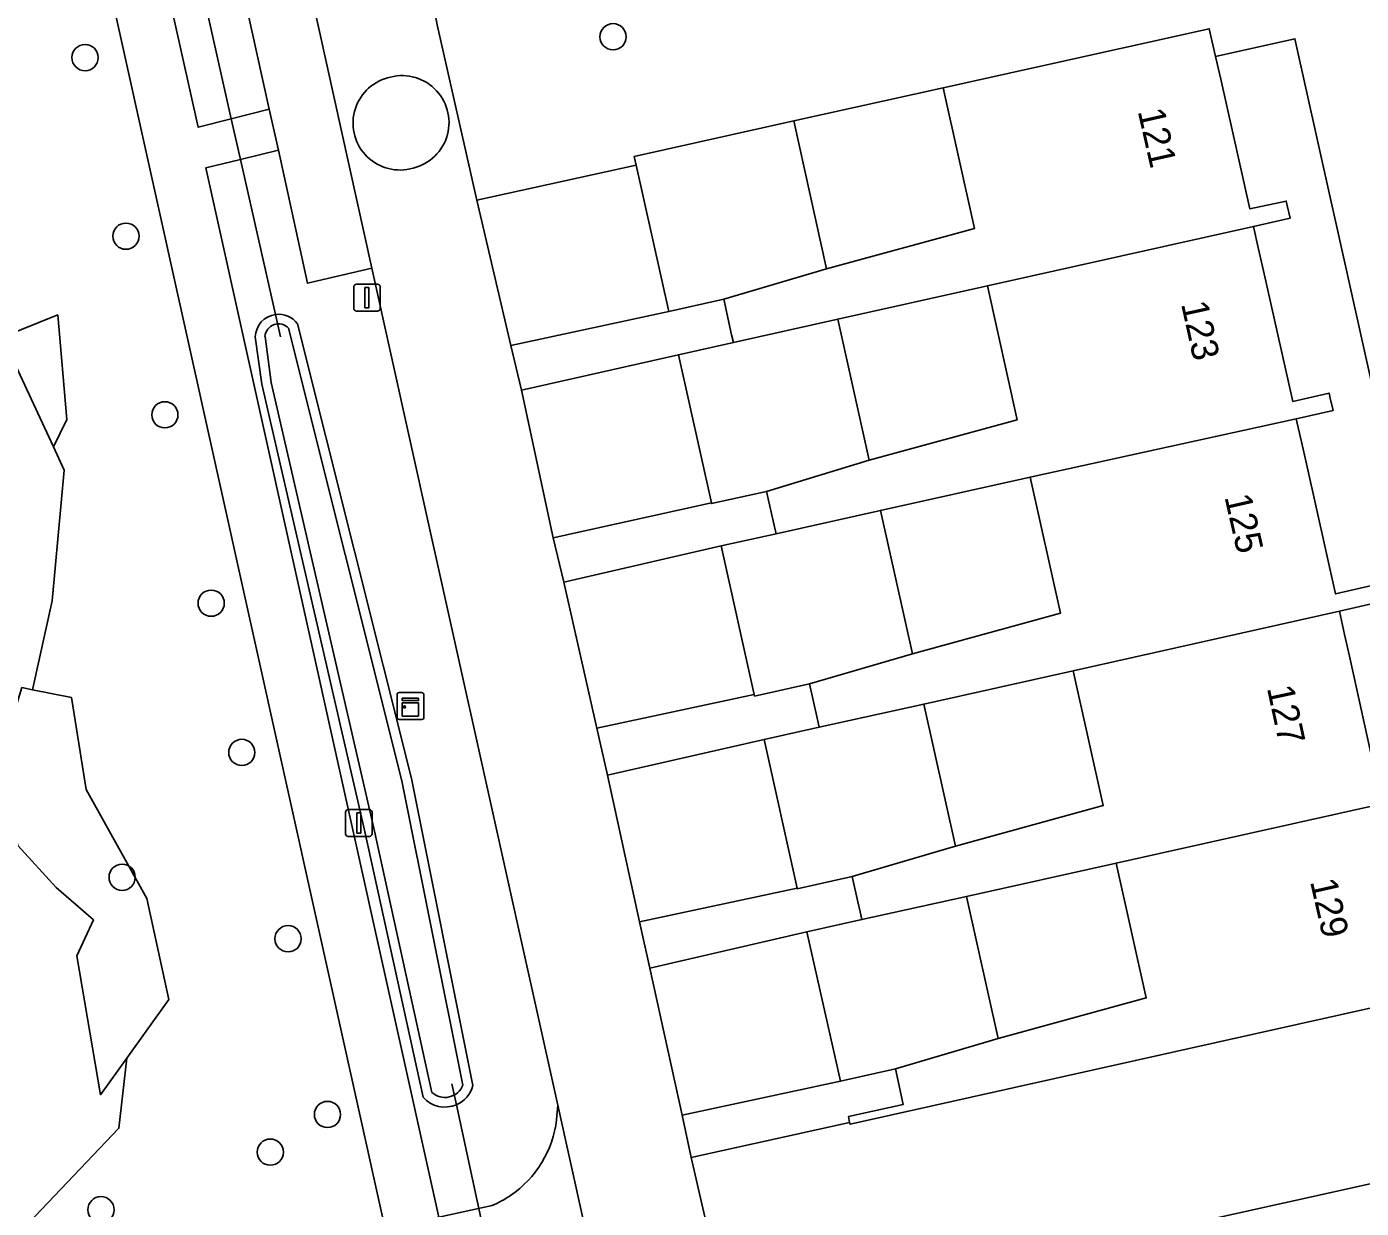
# Model space of a CAD drawing. Extents: x 156661 to 157576, y 383570 to 384425.
# Drawn here: x 156780.23 to 156829.98, y 383941.52 to 383985.58 of the extents above; entities that cross this region are included whole.
import ezdxf

# ---------------------------------------------------------------- set-up
doc = ezdxf.new("R2010")
doc.units = 0
for name, color, linetype in [('IMGEO_Berm_groen', 7, 'Continuous'), ('IMGEO_Boom', 7, 'Continuous'), ('IMGEO_Duiker', 7, 'Continuous'), ('IMGEO_Erf', 7, 'Continuous'), ('IMGEO_Groenvoorziening', 7, 'Continuous'), ('IMGEO_Kast', 7, 'Continuous'), ('IMGEO_Lichtmast', 7, 'Continuous'), ('IMGEO_Meer_plas_ven_vijver', 7, 'Continuous'), ('IMGEO_Muur', 7, 'Continuous'), ('IMGEO_Oever', 7, 'Continuous'), ('IMGEO_Pand', 7, 'Continuous'), ('IMGEO_Pand_nummerreeks', 7, 'Continuous'), ('IMGEO_Parkeervlak_open', 7, 'Continuous'), ('IMGEO_Rijbaan_lokaal_gesloten', 7, 'Continuous'), ('IMGEO_Rijbaan_lokaal_open', 7, 'Continuous'), ('IMGEO_Voetpad_open', 7, 'Continuous'), ('IMGEO_Waterloop', 7, 'Continuous')]:
    doc.layers.add(name, color=color, linetype=linetype)

msp = doc.modelspace()

# ---------------------------------------------------------------- linework, layer by layer
at = {"layer": 'IMGEO_Berm_groen'}
for points in [[(156795.637, 383965.148), (156795.252, 383966.882), (156793.102, 383976.569), (156790.698, 383976.013), (156789.615, 383980.975), (156788.201, 383980.63), (156786.905, 383980.313), (156795.59, 383941.189), (156797.583, 383941.621)], [(156790.324, 383974.498), (156794.571, 383957.54)], [(156795.006, 383945.664), (156792.825, 383955.613), (156788.991, 383972.249), (156788.754, 383974.011)], [(156799.984, 383944.824), (156800.028, 383945.365), (156795.637, 383965.148)], [(156794.571, 383957.54), (156796.861, 383946.093)]]:
    msp.add_lwpolyline(points, dxfattribs=at)
for centre, radius, start, end in [((156789.624, 383973.982), 0.871, 97.793, 178.0581), ((156789.622, 383973.979), 0.873, 36.4787, 97.6662), ((156795.822, 383946.369), 1.075, 293.447, 345.1249), ((156795.819, 383946.367), 1.075, 220.8788, 293.664), ((156796.012, 383945.301), 4.001, 304.3465, 353.1493), ((156796.056, 383945.213), 3.903, 293.0369, 304.5462)]:
    msp.add_arc(centre, radius, start, end, dxfattribs=at)
at = {"layer": 'IMGEO_Boom'}
for centre in [(156802.09, 383985.2), (156782.407, 383984.424), (156783.931, 383977.764), (156785.382, 383971.105), (156787.108, 383964.081), (156788.249, 383958.516), (156783.789, 383953.862), (156789.974, 383951.57), (156791.443, 383945.018), (156789.312, 383943.613), (156782.999, 383941.466)]:
    msp.add_circle(centre, 0.489, dxfattribs=at)
at = {"layer": 'IMGEO_Duiker'}
for points in [[(156789.693, 383974.016), (156789.506, 383974.844), (156788.201, 383980.63), (156787.859, 383982.142), (156786.48, 383988.253), (156786.291, 383989.092)], [(156796.083, 383946.154), (156796.25, 383945.383), (156797.626, 383939.03), (156797.937, 383937.594), (156799.164, 383931.925), (156799.323, 383931.192)]]:
    msp.add_lwpolyline(points, dxfattribs=at)
at = {"layer": 'IMGEO_Erf'}
for points in [[(156830.41, 383972.082), (156829.107, 383977.94), (156828.812, 383979.266), (156827.51, 383985.126), (156824.549, 383984.468), (156824.741, 383983.615), (156825.829, 383978.779), (156827.187, 383979.076), (156827.223, 383978.913), (156827.328, 383978.432), (156825.968, 383978.127), (156826.157, 383977.284), (156826.339, 383976.469), (156827.429, 383971.603), (156828.784, 383971.912), (156828.826, 383971.73), (156828.932, 383971.264), (156827.561, 383970.954), (156827.753, 383970.099), (156827.936, 383969.283), (156829.025, 383964.425), (156830.38, 383964.735)], [(156830.528, 383964.088), (156829.173, 383963.778), (156829.363, 383962.918), (156829.541, 383962.109), (156830.615, 383957.249)]]:
    msp.add_lwpolyline(points, dxfattribs=at)
for points in [[(156810.051, 383976.546), (156815.566, 383978.053), (156814.4, 383983.295), (156808.823, 383982.061)], [(156811.641, 383969.415), (156817.156, 383970.922), (156816.043, 383975.914), (156810.469, 383974.671)], [(156813.25, 383962.197), (156818.766, 383963.704), (156817.633, 383968.783), (156812.059, 383967.54)], [(156814.85, 383955.025), (156820.365, 383956.532), (156819.243, 383961.564), (156813.669, 383960.322)], [(156816.448, 383947.854), (156821.964, 383949.362), (156820.842, 383954.393), (156815.268, 383953.15)]]:
    msp.add_lwpolyline(points, close=True, dxfattribs=at)
at = {"layer": 'IMGEO_Groenvoorziening'}
for points in [[(156785.743, 384009.788), (156782.661, 384009.212), (156783.294, 384006.453), (156781.235, 384006.002), (156786.625, 383981.827), (156787.859, 383982.142), (156789.272, 383982.501), (156788.165, 383987.516), (156790.572, 383987.99)], [(156779.327, 383973.994), (156781.225, 383969.906), (156781.724, 383970.931), (156781.389, 383974.828)], [(156780.441, 383960.855), (156780.053, 383960.933), (156779.701, 383959.798), (156778.222, 383959.363), (156776.978, 383959.318), (156776.54, 383958.214), (156777.466, 383957.092), (156778.922, 383957.158), (156779.589, 383956.296), (156779.895, 383955.046), (156781.326, 383953.479), (156782.724, 383952.271), (156782.102, 383950.935), (156782.987, 383945.756), (156783.962, 383947.12), (156785.527, 383949.309), (156784.708, 383953.072), (156782.448, 383957.137), (156781.902, 383960.563)]]:
    msp.add_lwpolyline(points, close=True, dxfattribs=at)
for points in [[(156762.934, 383934.118), (156793.6, 383940.758), (156778.599, 384008.292)], [(156795.536, 383985.651), (156797.01, 383979.104), (156802.956, 383980.408), (156802.882, 383980.74), (156808.823, 383982.061), (156814.4, 383983.295), (156824.316, 383985.501), (156824.549, 383984.468), (156827.51, 383985.126), (156828.812, 383979.266), (156829.107, 383977.94), (156830.41, 383972.082)], [(156779.327, 383973.994), (156781.389, 383974.828), (156781.724, 383970.931), (156781.225, 383969.906), (156781.627, 383969.04), (156781.182, 383964.169), (156780.441, 383960.855), (156781.902, 383960.563), (156782.448, 383957.137), (156784.708, 383953.072), (156785.527, 383949.309), (156783.962, 383947.12), (156783.667, 383944.503), (156778.843, 383939.451)], [(156833.708, 383949.734), (156810.924, 383944.655), (156810.91, 383944.714), (156805.002, 383943.411), (156806.516, 383936.828), (156812.384, 383938.086), (156812.309, 383938.432), (156818.242, 383939.753), (156823.818, 383940.987), (156833.736, 383943.193)]]:
    msp.add_lwpolyline(points, dxfattribs=at)
at = {"layer": 'IMGEO_Kast'}
for p, q in [((156794.112, 383960.747), (156794.953, 383960.747)), ((156794.953, 383960.747), (156794.112, 383960.747)), ((156794.037, 383959.822), (156794.037, 383960.663)), ((156794.037, 383960.663), (156794.037, 383959.822)), ((156795.037, 383960.672), (156795.037, 383959.831)), ((156795.037, 383959.831), (156795.037, 383960.672)), ((156794.962, 383959.747), (156794.121, 383959.747)), ((156794.121, 383959.747), (156794.962, 383959.747))]:
    msp.add_line(p, q, dxfattribs=at)
for points in [[(156794.232, 383960.537), (156794.832, 383960.537), (156794.832, 383960.452), (156794.232, 383960.452), (156794.232, 383960.537)], [(156794.232, 383960.362), (156794.832, 383960.362), (156794.832, 383959.873), (156794.232, 383959.873), (156794.232, 383960.362)]]:
    msp.add_lwpolyline(points, dxfattribs=at)
msp.add_circle((156794.316, 383960.211), 0.0377, dxfattribs=at)
for centre, start, end in [((156794.115, 383960.669), 92.4484, 184.2845), ((156794.115, 383960.669), 92.4484, 184.2845), ((156794.959, 383960.669), 2.4484, 94.2845), ((156794.959, 383960.669), 2.4484, 94.2845), ((156794.115, 383959.825), 182.4484, 274.2845), ((156794.115, 383959.825), 182.4484, 274.2845), ((156794.959, 383959.825), 272.4484, 4.2845), ((156794.959, 383959.825), 272.4484, 4.2845)]:
    msp.add_arc(centre, 0.0779, start, end, dxfattribs=at)
at = {"layer": 'IMGEO_Lichtmast'}
for p, q in [((156792.421, 383975.072), (156792.421, 383975.872)), ((156792.421, 383975.872), (156792.421, 383975.072)), ((156792.521, 383975.972), (156793.311, 383975.972)), ((156793.311, 383975.972), (156792.521, 383975.972)), ((156793.411, 383975.872), (156793.411, 383975.072)), ((156793.411, 383975.072), (156793.411, 383975.872)), ((156793.311, 383974.972), (156792.521, 383974.972)), ((156792.521, 383974.972), (156793.311, 383974.972)), ((156792.115, 383955.485), (156792.115, 383956.285)), ((156792.115, 383956.285), (156792.115, 383955.485)), ((156792.215, 383956.385), (156793.005, 383956.385)), ((156793.005, 383956.385), (156792.215, 383956.385)), ((156793.105, 383956.285), (156793.105, 383955.485)), ((156793.105, 383955.485), (156793.105, 383956.285)), ((156793.005, 383955.385), (156792.215, 383955.385)), ((156792.215, 383955.385), (156793.005, 383955.385))]:
    msp.add_line(p, q, dxfattribs=at)
for points in [[(156792.841, 383975.847), (156792.991, 383975.847), (156792.991, 383975.097), (156792.841, 383975.097), (156792.841, 383975.847)], [(156792.535, 383956.26), (156792.685, 383956.26), (156792.685, 383955.51), (156792.535, 383955.51), (156792.535, 383956.26)]]:
    msp.add_lwpolyline(points, dxfattribs=at)
for centre, start, end in [((156792.521, 383975.872), 90, 180), ((156792.521, 383975.872), 90, 180), ((156793.311, 383975.872), 0, 90), ((156793.311, 383975.872), 360, 90), ((156792.521, 383975.072), 180, 270), ((156792.521, 383975.072), 180, 270), ((156793.311, 383975.072), 270, 0), ((156793.311, 383975.072), 270, 0), ((156792.215, 383956.285), 90, 180), ((156792.215, 383956.285), 90, 180), ((156793.005, 383956.285), 0, 90), ((156793.005, 383956.285), 360, 90), ((156792.215, 383955.485), 180, 270), ((156792.215, 383955.485), 180, 270), ((156793.005, 383955.485), 270, 0), ((156793.005, 383955.485), 270, 0)]:
    msp.add_arc(centre, 0.1, start, end, dxfattribs=at)
at = {"layer": 'IMGEO_Meer_plas_ven_vijver'}
for points in [[(156780.053, 383960.933), (156780.441, 383960.855), (156781.182, 383964.169), (156781.627, 383969.04), (156781.225, 383969.906), (156779.327, 383973.994)], [(156778.843, 383939.451), (156783.667, 383944.503), (156783.962, 383947.12), (156782.987, 383945.756), (156782.102, 383950.935), (156782.724, 383952.271), (156781.326, 383953.479), (156779.895, 383955.046)]]:
    msp.add_lwpolyline(points, dxfattribs=at)
at = {"layer": 'IMGEO_Muur'}
for points in [[(156824.549, 383984.468), (156827.51, 383985.126), (156828.812, 383979.266)], [(156808.823, 383982.061), (156814.4, 383983.295)], [(156829.107, 383977.94), (156830.41, 383972.082)]]:
    msp.add_lwpolyline(points, dxfattribs=at)
at = {"layer": 'IMGEO_Oever'}
for points in [[(156789.995, 383974.332), (156794.22, 383957.461)], [(156796.861, 383946.093), (156794.571, 383957.54), (156790.324, 383974.498)], [(156788.754, 383974.011), (156788.991, 383972.249), (156792.825, 383955.613), (156795.006, 383945.664)], [(156795.335, 383945.84), (156793.176, 383955.692), (156789.345, 383972.313), (156789.115, 383974.025)], [(156794.22, 383957.461), (156796.491, 383946.113)]]:
    msp.add_lwpolyline(points, dxfattribs=at)
for centre, radius, start, end in [((156789.624, 383973.982), 0.871, 97.793, 178.0581), ((156789.622, 383973.979), 0.873, 36.4787, 97.6662), ((156789.621, 383973.988), 0.508, 42.6536, 175.8105), ((156795.82, 383946.372), 0.72, 227.6875, 338.8874), ((156795.822, 383946.369), 1.075, 293.447, 345.1249), ((156795.819, 383946.367), 1.075, 220.8788, 293.664)]:
    msp.add_arc(centre, radius, start, end, dxfattribs=at)
at = {"layer": 'IMGEO_Pand'}
for points in [[(156825.968, 383978.127), (156827.328, 383978.432), (156827.223, 383978.913), (156827.187, 383979.076), (156825.829, 383978.779), (156824.741, 383983.615), (156824.549, 383984.468), (156824.316, 383985.501), (156814.4, 383983.295), (156815.566, 383978.053), (156810.051, 383976.546), (156806.217, 383975.415), (156806.511, 383974.087), (156806.574, 383973.803), (156810.469, 383974.671), (156816.043, 383975.914)], [(156810.051, 383976.546), (156808.823, 383982.061), (156802.882, 383980.74), (156802.956, 383980.408), (156804.167, 383974.96), (156806.217, 383975.415)], [(156827.561, 383970.954), (156828.932, 383971.264), (156828.826, 383971.73), (156828.784, 383971.912), (156827.429, 383971.603), (156826.339, 383976.469), (156826.157, 383977.284), (156825.968, 383978.127), (156816.043, 383975.914), (156817.156, 383970.922), (156811.641, 383969.415), (156807.812, 383968.25), (156808.058, 383967.148), (156808.108, 383966.922), (156808.164, 383966.672), (156812.059, 383967.54), (156817.633, 383968.783)], [(156810.469, 383974.671), (156806.574, 383973.803), (156804.525, 383973.346), (156805.754, 383967.828), (156805.762, 383967.793), (156807.812, 383968.25), (156811.641, 383969.415)], [(156829.173, 383963.778), (156830.528, 383964.088), (156830.426, 383964.533), (156830.38, 383964.735), (156829.025, 383964.425), (156827.936, 383969.283), (156827.753, 383970.099), (156827.561, 383970.954), (156817.633, 383968.783), (156818.766, 383963.704), (156813.25, 383962.197), (156809.413, 383961.077), (156809.71, 383959.75), (156809.776, 383959.454), (156813.669, 383960.322), (156819.243, 383961.564)], [(156812.059, 383967.54), (156808.164, 383966.672), (156806.114, 383966.215), (156807.352, 383960.672), (156807.364, 383960.619), (156809.413, 383961.077), (156813.25, 383962.197)], [(156830.76, 383956.604), (156832.116, 383956.908), (156832.016, 383957.354), (156831.971, 383957.553), (156830.615, 383957.249), (156829.541, 383962.109), (156829.363, 383962.918), (156829.173, 383963.778), (156819.243, 383961.564), (156820.365, 383956.532), (156814.85, 383955.025), (156811.004, 383953.894), (156811.217, 383952.951), (156811.304, 383952.568), (156811.369, 383952.281), (156815.268, 383953.15), (156820.842, 383954.393)], [(156813.669, 383960.322), (156809.776, 383959.454), (156807.726, 383958.997), (156808.95, 383953.454), (156808.956, 383953.43), (156811.004, 383953.894), (156814.85, 383955.025)], [(156816.448, 383947.854), (156812.614, 383946.722), (156812.91, 383945.395), (156810.861, 383944.938), (156810.91, 383944.714), (156810.924, 383944.655), (156833.708, 383949.734), (156833.616, 383950.172), (156833.57, 383950.388), (156832.21, 383950.101), (156831.132, 383954.932), (156830.952, 383955.74), (156830.76, 383956.604), (156820.842, 383954.393), (156821.964, 383949.362)], [(156815.268, 383953.15), (156811.369, 383952.281), (156809.319, 383951.824), (156810.565, 383946.265), (156812.614, 383946.722), (156816.448, 383947.854)], [(156835.377, 383935.827), (156836.733, 383936.134), (156836.622, 383936.62), (156836.586, 383936.783), (156835.23, 383936.476), (156834.15, 383941.33), (156833.955, 383942.205), (156833.736, 383943.193), (156823.818, 383940.987), (156824.985, 383935.745), (156819.469, 383934.238), (156815.612, 383933.105), (156815.84, 383932.096), (156815.91, 383931.788), (156815.972, 383931.515), (156819.89, 383932.386), (156825.454, 383933.622)]]:
    msp.add_lwpolyline(points, close=True, dxfattribs=at)
at = {"layer": 'IMGEO_Parkeervlak_open'}
for points in [[(156793.102, 383976.569), (156790.572, 383987.99), (156788.165, 383987.516), (156789.272, 383982.501), (156789.615, 383980.975), (156790.698, 383976.013)], [(156802.956, 383980.408), (156797.01, 383979.104), (156798.285, 383973.693), (156804.167, 383974.96)], [(156804.525, 383973.346), (156798.681, 383972.018), (156799.852, 383966.521), (156805.754, 383967.828)], [(156806.114, 383966.215), (156800.258, 383964.867), (156801.484, 383959.425), (156807.352, 383960.672)], [(156807.726, 383958.997), (156801.882, 383957.669), (156803.072, 383952.198), (156808.95, 383953.454)], [(156809.319, 383951.824), (156803.456, 383950.473), (156804.664, 383944.993), (156810.565, 383946.265)]]:
    msp.add_lwpolyline(points, close=True, dxfattribs=at)
at = {"layer": 'IMGEO_Rijbaan_lokaal_gesloten'}
for points in [[(156801.775, 383936.87), (156801.949, 383936.722), (156800.028, 383945.365), (156799.984, 383944.824)], [(156797.583, 383941.621), (156795.59, 383941.189), (156793.6, 383940.758), (156762.934, 383934.118)]]:
    msp.add_lwpolyline(points, dxfattribs=at)
for centre, radius, start, end in [((156796.012, 383945.301), 4.001, 304.3465, 353.1493), ((156796.056, 383945.213), 3.903, 293.0369, 304.5462)]:
    msp.add_arc(centre, radius, start, end, dxfattribs=at)
at = {"layer": 'IMGEO_Rijbaan_lokaal_open'}
for points in [[(156781.479, 384029.084), (156783.818, 384018.482), (156783.89, 384018.153), (156784.912, 384013.537), (156785.155, 384012.442), (156785.743, 384009.788), (156790.572, 383987.99), (156793.102, 383976.569), (156795.252, 383966.882), (156795.637, 383965.148), (156800.028, 383945.365), (156801.949, 383936.722), (156802.676, 383933.449), (156808.224, 383908.678)], [(156803.072, 383952.198), (156801.882, 383957.669), (156801.484, 383959.425), (156800.258, 383964.867), (156799.852, 383966.521), (156798.681, 383972.018), (156798.285, 383973.693), (156797.01, 383979.104), (156795.536, 383985.651), (156795.233, 383987.245), (156794.036, 383992.786), (156793.634, 383994.464), (156792.461, 383999.986), (156792.018, 384001.647), (156790.816, 384007.092), (156790.471, 384008.784), (156789.406, 384013.718), (156789.126, 384015.149), (156787.052, 384024.701)], [(156812.552, 383909.758), (156812.396, 383910.435), (156812.023, 383911.93), (156810.873, 383917.164), (156809.69, 383922.576), (156809.293, 383924.239), (156808.084, 383929.719), (156807.701, 383931.447), (156806.516, 383936.828), (156805.002, 383943.411), (156804.664, 383944.993), (156803.456, 383950.473), (156803.072, 383952.198)]]:
    msp.add_lwpolyline(points, dxfattribs=at)
for centre, radius, start, end in [((156794.143, 383981.98), 1.748, 105.3821, 286.2926), ((156794.143, 383981.98), 1.748, 105.3821, 286.2926), ((156794.225, 383982.003), 1.749, 283.4805, 108.1942), ((156794.225, 383982.003), 1.749, 283.4805, 108.1942)]:
    msp.add_arc(centre, radius, start, end, dxfattribs=at)
at = {"layer": 'IMGEO_Voetpad_open'}
for points in [[(156781.235, 384006.002), (156783.294, 384006.453), (156782.661, 384009.212), (156782.408, 384009.165), (156778.599, 384008.292), (156793.6, 383940.758), (156795.59, 383941.189), (156786.905, 383980.313), (156788.201, 383980.63), (156789.615, 383980.975), (156789.272, 383982.501), (156787.859, 383982.142), (156786.625, 383981.827)], [(156806.574, 383973.803), (156806.511, 383974.087), (156806.217, 383975.415), (156804.167, 383974.96), (156798.285, 383973.693), (156798.681, 383972.018), (156804.525, 383973.346)], [(156808.164, 383966.672), (156808.108, 383966.922), (156808.058, 383967.148), (156807.812, 383968.25), (156805.762, 383967.793), (156805.754, 383967.828), (156799.852, 383966.521), (156800.258, 383964.867), (156806.114, 383966.215)], [(156809.776, 383959.454), (156809.71, 383959.75), (156809.413, 383961.077), (156807.364, 383960.619), (156807.352, 383960.672), (156801.484, 383959.425), (156801.882, 383957.669), (156807.726, 383958.997)], [(156811.369, 383952.281), (156811.304, 383952.568), (156811.217, 383952.951), (156811.004, 383953.894), (156808.956, 383953.43), (156808.95, 383953.454), (156803.072, 383952.198), (156803.456, 383950.473), (156809.319, 383951.824)], [(156812.614, 383946.722), (156810.565, 383946.265), (156804.664, 383944.993), (156805.002, 383943.411), (156810.91, 383944.714), (156810.861, 383944.938), (156812.91, 383945.395)]]:
    msp.add_lwpolyline(points, close=True, dxfattribs=at)
at = {"layer": 'IMGEO_Waterloop'}
for points in [[(156794.22, 383957.461), (156789.995, 383974.332)], [(156789.115, 383974.025), (156789.345, 383972.313), (156793.176, 383955.692), (156795.335, 383945.84)], [(156796.491, 383946.113), (156794.22, 383957.461)]]:
    msp.add_lwpolyline(points, dxfattribs=at)
for centre, radius, start, end in [((156789.621, 383973.988), 0.508, 42.6536, 175.8105), ((156795.82, 383946.372), 0.72, 227.6875, 338.8874)]:
    msp.add_arc(centre, radius, start, end, dxfattribs=at)

# ---------------------------------------------------------------- texts
at = {"layer": 'IMGEO_Pand_nummerreeks'}
for s, rotation, p in [('121', 282.7939, (156821.644, 383982.429)), ('123', 282.4444, (156823.261, 383975.242)), ('125', 282.8799, (156824.878, 383968.045)), ('127', 282.1236, (156826.462, 383960.921)), ('129', 282.7339, (156828.069, 383953.708))]:
    msp.add_text(s, height=1, rotation=rotation, dxfattribs=at).set_placement(p)

doc.saveas('drawing.dxf')
